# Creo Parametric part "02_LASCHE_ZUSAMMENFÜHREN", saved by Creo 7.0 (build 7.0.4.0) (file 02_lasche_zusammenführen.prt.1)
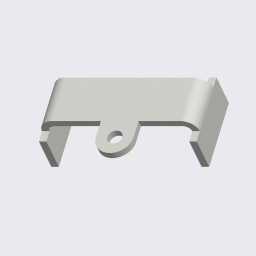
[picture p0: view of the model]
Units: millimeter Kilogram Sec (mmKs); MM, KILOGRAM, SECS
Materials in the file: S235JRG2

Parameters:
  SMT_PART_BEND_ALLOW_FACTOR_TYPE = "Y FACTOR"
  SMT_DFLT_RADIUS_SIDE = "Inside"
  SMT_DFLT_CRNR_REL_TYPE = "V Notch"
  SMT_DFLT_CRNR_REL_DEPTH_TYPE = "Blind"
  SMT_DFLT_BEND_REL_TYPE = "Rip"
  SMT_DFLT_BEND_REL_DEPTH_TYPE = "Up to Bend"
  SMT_DFLT_EDGE_TREA_TYPE = "Open"
  PTC_MATERIAL_NAME = "S235JRG2"
  MATERIAL = "S235JRG2"
  BENENNUNG = "XXX"
  DATUM = "XX.XX.XX"
  ERSTELLER = "ARINDA"
  TEILETYP = "Fertigungsteil"
  SELECT_EN_NAME = "S235JRG2"
  SELECT_DIN_NAME = "RSt37-2"
  SELECT_DIN_NUMBER = "1.0038"
  SELECT_ASTM_NAME = "A 283 M Grade 2"
  MATERIAL_GROUP = "ME_ST_Baustahl"
  STANDARD_EN_DELIVERYSPEC = "DIN EN 10025"
  STANDARD_DIN_DELIVERYSPEC = "DIN 17100"
  COPY_GEOM_ORIGIN_TYPE = "Part"

Other parameters: SMT_THICKNESS, SMT_PART_BEND_ALLOWANCE_FACTOR, SMT_UPDATE_BEND_ALLOW_INFO, SMT_DFLT_BEND_RADIUS, SMT_DFLT_BEND_ANGLE, SMT_DFLT_CRNR_REL_WIDTH, SMT_DFLT_CRNR_REL_DEPTH, SMT_DFLT_BEND_REL_WIDTH, SMT_DFLT_BEND_REL_DEPTH, SMT_DFLT_BEND_REL_ANGLE, SMT_GAP, SMT_DFLT_EDGE_TREA_WIDTH, SMT_DFLT_MITER_CUT_WIDTH, SMT_DFLT_MITER_CUT_OFFSET, MASSE, SMT_DFLT_BEND_REL_LENGTH, D4, D6

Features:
  1. coordinate system
  2. datum plane "DTM1", "T_RECHTS_Y-Z"
  3. datum plane "DTM2", "T_OBEN_X-Z"
  4. datum plane "DTM3", "T_VORNE_X-Y"
  5. datum axis "A_1"
  6. datum axis "A_2"
  7. datum axis "A_3"
  8. feature "Externe Kopiegeom ID 31"
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
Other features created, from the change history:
  feature "Externe Kopiegeom ID 42"
  feature "Versatz 1(Erste Lasche)"
  feature "Versatz 2"
  feature "Profil 1"
  feature "Laschen Zusammenführen 1" (2 times)
  fill "Planar 1"

Other named items: T_BASIS, A_X-ACHSE, A_Y-ACHSE, A_Z-ACHSE

Layers: 00_STD-ACHSEN, 00_STD-EBENEN, 00_STD-KOORDSYS, 01_ACHSEN, SAMMELFLÄCHEN, VOLUMENGEOMETRIE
